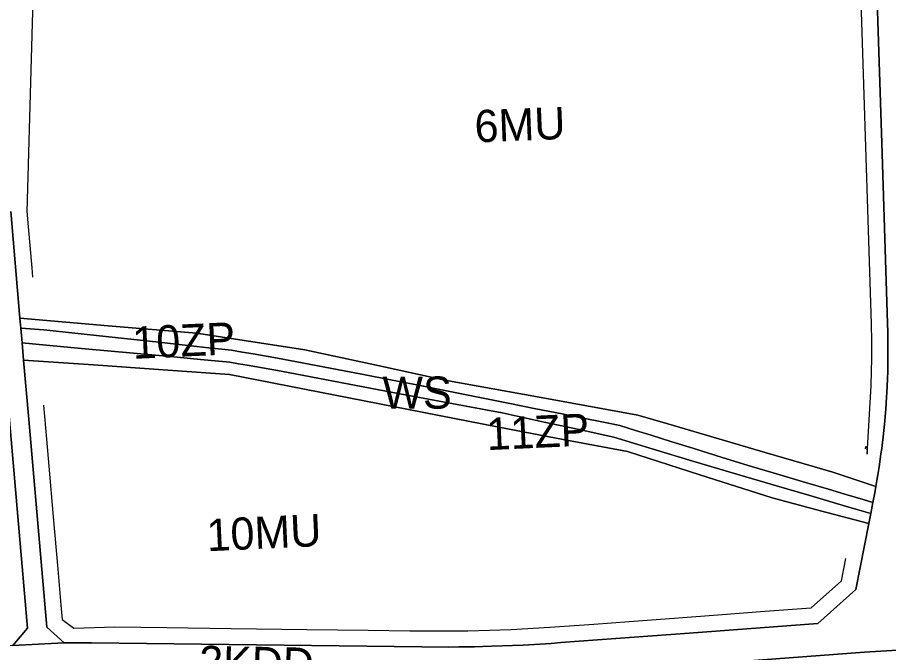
# Model space of a CAD drawing. Extents: x 7418021 to 7419743, y 5540231 to 5541685.
# Drawn here: x 7419069.1 to 7419339.9, y 5540508.6 to 5540706.1 of the extents above; entities that cross this region are included whole.
import ezdxf

# ---------------------------------------------------------------- set-up
doc = ezdxf.new("R2010")
doc.units = 0
for name, color, linetype in [('linie_rozgraniczajace', 7, 'Continuous'), ('linie_zabudowy_nieprzekraczalne', 7, 'Continuous'), ('oznaczenia_przeznaczen', 7, 'Continuous')]:
    doc.layers.add(name, color=color, linetype=linetype)

msp = doc.modelspace()

# ---------------------------------------------------------------- linework, layer by layer
at = {"layer": 'linie_rozgraniczajace'}
for points in [[(7419336.33, 5540711.28), (7419337.76, 5540666.96), (7419339.58, 5540611.01), (7419339.63, 5540608.2), (7419339.69, 5540605.39), (7419339.69, 5540602.6), (7419339.68, 5540599.81), (7419339.64, 5540597.92), (7419339.6, 5540596.04), (7419339.51, 5540593.68), (7419339.42, 5540591.32), (7419339.33, 5540589.6), (7419339.23, 5540587.87), (7419338.98, 5540584.26), (7419338.58, 5540579.65), (7419338.38, 5540577.68), (7419338.17, 5540575.7), (7419337.95, 5540573.89), (7419337.73, 5540572.07), (7419337.51, 5540570.43), (7419337.29, 5540568.79), (7419336.92, 5540566.32), (7419336.54, 5540563.85), (7419336.24, 5540562.07), (7419335.94, 5540560.28), (7419322.52, 5540564.68), (7419301.55, 5540570.84), (7419271.24, 5540579.7), (7419261.92, 5540582.4), (7419231.92, 5540587.88), (7419201.91, 5540593.35), (7419180.19, 5540598.05), (7419158.46, 5540602.74), (7419141.6, 5540605.33), (7419124.73, 5540607.91), (7419097.29, 5540610.25), (7419069.85, 5540612.59), (7419066.98, 5540645.75)], [(7419067.63, 5540510.82), (7419083.62, 5540511.65), (7419092.09, 5540511.68), (7419143.41, 5540511.02), (7419194.73, 5540510.36), (7419203.14, 5540510.33), (7419206.29, 5540510.35), (7419211.12, 5540510.42), (7419213.61, 5540510.48), (7419216.4, 5540510.56), (7419219.75, 5540510.67), (7419222.99, 5540510.8), (7419226.26, 5540510.96), (7419235.02, 5540511.48), (7419237.94, 5540511.69), (7419277.9, 5540514.67), (7419317.85, 5540517.65), (7419323.79, 5540522.93), (7419329.73, 5540528.21), (7419333.72, 5540548.71), (7419334.34, 5540551.87), (7419335, 5540555.32), (7419335.57, 5540558.3), (7419335.94, 5540560.28), (7419336.24, 5540562.07), (7419336.54, 5540563.85), (7419336.92, 5540566.32), (7419337.29, 5540568.79), (7419337.51, 5540570.43), (7419337.73, 5540572.07), (7419337.95, 5540573.89), (7419338.17, 5540575.7), (7419338.38, 5540577.68), (7419338.58, 5540579.65), (7419338.98, 5540584.26), (7419339.23, 5540587.87), (7419339.33, 5540589.6), (7419339.42, 5540591.32), (7419339.51, 5540593.68), (7419339.6, 5540596.04), (7419339.64, 5540597.92), (7419339.68, 5540599.81), (7419339.69, 5540602.6), (7419339.69, 5540605.39), (7419339.63, 5540608.2), (7419339.58, 5540611.01), (7419337.76, 5540666.96), (7419336.33, 5540711.28)], [(7419066.98, 5540645.75), (7419069.85, 5540612.59), (7419070.12, 5540609.45), (7419070.52, 5540604.88), (7419070.98, 5540599.56), (7419072.58, 5540581.12), (7419078.18, 5540516.49), (7419083.62, 5540511.65), (7419067.63, 5540510.82), (7419072.18, 5540516.17), (7419066.58, 5540580.83)], [(7419393.57, 5540512.42), (7419332.34, 5540508.71), (7419285.51, 5540505.21)], [(7419285.51, 5540505.21), (7419332.34, 5540508.71), (7419393.57, 5540512.42)]]:
    msp.add_lwpolyline(points, dxfattribs=at)
for points in [[(7419069.85, 5540612.59), (7419097.29, 5540610.25), (7419124.73, 5540607.91), (7419141.6, 5540605.33), (7419158.46, 5540602.74), (7419180.19, 5540598.05), (7419201.91, 5540593.35), (7419231.92, 5540587.88), (7419261.92, 5540582.4), (7419271.24, 5540579.7), (7419301.55, 5540570.84), (7419322.52, 5540564.68), (7419335.94, 5540560.28), (7419335.57, 5540558.3), (7419335, 5540555.32), (7419331.92, 5540556.22), (7419326.24, 5540557.9), (7419321.22, 5540559.37), (7419314.09, 5540561.49), (7419304.04, 5540564.47), (7419297.27, 5540566.48), (7419288.14, 5540569.3), (7419279.02, 5540572.12), (7419272.53, 5540574.15), (7419266.03, 5540576.17), (7419261.19, 5540577.68), (7419256.35, 5540579.19), (7419252.76, 5540579.94), (7419249.16, 5540580.68), (7419243.79, 5540581.75), (7419238.42, 5540582.81), (7419230.26, 5540584.43), (7419222.1, 5540586.05), (7419212.29, 5540588), (7419202.47, 5540589.95), (7419193.74, 5540591.78), (7419189.39, 5540592.6), (7419185.04, 5540593.41), (7419176.15, 5540595.13), (7419166.84, 5540596.94), (7419157.53, 5540598.75), (7419149.93, 5540600.11), (7419142.33, 5540601.48), (7419138.96, 5540602.06), (7419135.59, 5540602.63), (7419131.56, 5540603.07), (7419127.54, 5540603.5), (7419112.98, 5540605.09), (7419096.55, 5540606.87), (7419077.26, 5540608.95), (7419070.12, 5540609.45)], [(7419070.12, 5540609.45), (7419077.26, 5540608.95), (7419096.55, 5540606.87), (7419112.98, 5540605.09), (7419127.54, 5540603.5), (7419131.56, 5540603.07), (7419135.59, 5540602.63), (7419138.96, 5540602.06), (7419142.33, 5540601.48), (7419149.93, 5540600.11), (7419157.53, 5540598.75), (7419166.84, 5540596.94), (7419176.15, 5540595.13), (7419185.04, 5540593.41), (7419189.39, 5540592.6), (7419193.74, 5540591.78), (7419202.47, 5540589.95), (7419212.29, 5540588), (7419222.1, 5540586.05), (7419230.26, 5540584.43), (7419238.42, 5540582.81), (7419243.79, 5540581.75), (7419249.16, 5540580.68), (7419252.76, 5540579.94), (7419256.35, 5540579.19), (7419261.19, 5540577.68), (7419266.03, 5540576.17), (7419272.53, 5540574.15), (7419279.02, 5540572.12), (7419288.14, 5540569.3), (7419297.27, 5540566.48), (7419304.04, 5540564.47), (7419314.09, 5540561.49), (7419321.22, 5540559.37), (7419326.24, 5540557.9), (7419331.92, 5540556.22), (7419335, 5540555.32), (7419334.34, 5540551.87), (7419330.04, 5540553.13), (7419325.74, 5540554.39), (7419315.36, 5540557.43), (7419304.98, 5540560.47), (7419292.01, 5540564.32), (7419279.05, 5540568.16), (7419266.74, 5540571.88), (7419254.44, 5540575.61), (7419243.65, 5540577.94), (7419232.85, 5540580.28), (7419226.3, 5540581.7), (7419219.74, 5540583.12), (7419214.7, 5540584.05), (7419187.95, 5540589.08), (7419151.06, 5540596.15), (7419145.26, 5540597.15), (7419140.48, 5540597.97), (7419137.77, 5540598.43), (7419135.05, 5540598.9), (7419132.8, 5540599.11), (7419130.55, 5540599.32), (7419128.24, 5540599.53), (7419125.93, 5540599.75), (7419117.72, 5540600.52), (7419105.16, 5540601.69), (7419090.08, 5540603.1), (7419077.99, 5540604.23), (7419070.52, 5540604.88)], [(7418938.17, 5540602.64), (7418963.79, 5540604.94), (7418989.41, 5540607.25), (7419027.14, 5540603.92), (7419064.86, 5540600.6), (7419066.58, 5540580.83), (7419072.18, 5540516.17), (7419067.63, 5540510.82), (7419055.07, 5540509.46), (7418984.43, 5540500.04), (7418913.79, 5540490.61), (7418910.2, 5540494.76), (7418921.59, 5540534.82), (7418932.97, 5540574.89), (7418935.14, 5540583.49), (7418936.07, 5540587.9), (7418936.64, 5540591.04), (7418937.19, 5540594.46), (7418937.41, 5540596.09), (7418937.82, 5540599.28), (7418938, 5540600.85)], [(7419070.52, 5540604.88), (7419077.99, 5540604.23), (7419090.08, 5540603.1), (7419105.16, 5540601.69), (7419117.72, 5540600.52), (7419125.93, 5540599.75), (7419128.24, 5540599.53), (7419130.55, 5540599.32), (7419132.8, 5540599.11), (7419135.05, 5540598.9), (7419137.77, 5540598.43), (7419140.48, 5540597.97), (7419145.26, 5540597.15), (7419151.06, 5540596.15), (7419187.95, 5540589.08), (7419214.7, 5540584.05), (7419219.74, 5540583.12), (7419226.3, 5540581.7), (7419232.85, 5540580.28), (7419243.65, 5540577.94), (7419254.44, 5540575.61), (7419266.74, 5540571.88), (7419279.05, 5540568.16), (7419292.01, 5540564.32), (7419304.98, 5540560.47), (7419315.36, 5540557.43), (7419325.74, 5540554.39), (7419330.04, 5540553.13), (7419334.34, 5540551.87), (7419333.72, 5540548.71), (7419318.68, 5540552.69), (7419303.65, 5540556.68), (7419281.17, 5540563.88), (7419258.7, 5540571.08), (7419238.71, 5540574.88), (7419218.72, 5540578.67), (7419176.88, 5540586.87), (7419135.04, 5540595.07), (7419124.71, 5540595.81), (7419114.38, 5540596.55), (7419092.68, 5540598.05), (7419070.98, 5540599.56)], [(7419070.98, 5540599.56), (7419092.68, 5540598.05), (7419114.38, 5540596.55), (7419124.71, 5540595.81), (7419135.04, 5540595.07), (7419176.88, 5540586.87), (7419218.72, 5540578.67), (7419238.71, 5540574.88), (7419258.7, 5540571.08), (7419281.17, 5540563.88), (7419303.65, 5540556.68), (7419318.68, 5540552.69), (7419333.72, 5540548.71), (7419329.73, 5540528.21), (7419323.79, 5540522.93), (7419317.85, 5540517.65), (7419277.9, 5540514.67), (7419237.94, 5540511.69), (7419235.02, 5540511.48), (7419226.26, 5540510.96), (7419222.99, 5540510.8), (7419219.75, 5540510.67), (7419216.4, 5540510.56), (7419213.61, 5540510.48), (7419211.12, 5540510.42), (7419206.29, 5540510.35), (7419203.14, 5540510.33), (7419194.73, 5540510.36), (7419143.41, 5540511.02), (7419092.09, 5540511.68), (7419083.62, 5540511.65), (7419078.18, 5540516.49), (7419072.58, 5540581.12)]]:
    msp.add_lwpolyline(points, close=True, dxfattribs=at)
at = {"layer": 'linie_zabudowy_nieprzekraczalne'}
for points in [[(7419075.71, 5540777.67), (7419071.98, 5540645.61)], [(7419334.58, 5540610.85), (7419331.23, 5540714.49)], [(7419071.99, 5540645.85), (7419072.41, 5540641)], [(7419072.41, 5540641), (7419073.52, 5540628.19)], [(7419073.52, 5540628.19), (7419073.76, 5540625.36)], [(7419334.7, 5540605.34), (7419334.58, 5540610.91)], [(7419334.69, 5540599.87), (7419334.7, 5540605.34)], [(7419334.61, 5540596.19), (7419334.69, 5540599.87)], [(7419334.43, 5540591.55), (7419334.61, 5540596.19)], [(7419333.26, 5540570.29), (7419334.43, 5540591.55)], [(7419077.21, 5540585.58), (7419078.13, 5540574.95)], [(7419078.13, 5540574.95), (7419078.86, 5540566.57)], [(7419332.68, 5540571.97), (7419332.78, 5540572.7)], [(7419332.78, 5540572.7), (7419332.8, 5540572.39)], [(7419332.8, 5540572.39), (7419332.97, 5540572.72)], [(7419332.97, 5540572.72), (7419333.16, 5540572.59)], [(7419333.16, 5540572.59), (7419333.26, 5540570.29)], [(7419078.86, 5540566.57), (7419080.22, 5540550.85)], [(7419080.22, 5540550.85), (7419081.64, 5540534.5)], [(7419325.24, 5540530.91), (7419326.55, 5540537.83)], [(7419081.64, 5540534.5), (7419082.6, 5540523.37)], [(7419315.8, 5540522.51), (7419325.24, 5540530.91)], [(7419082.6, 5540523.37), (7419082.99, 5540518.9)], [(7419286.79, 5540520.35), (7419301.43, 5540521.44)], [(7419301.43, 5540521.44), (7419315.8, 5540522.51)], [(7419082.99, 5540518.9), (7419086.6, 5540516.24)], [(7419259.22, 5540518.29), (7419274.6, 5540519.44)], [(7419274.6, 5540519.44), (7419286.79, 5540520.35)], [(7419086.6, 5540516.24), (7419099.34, 5540516.59)], [(7419099.34, 5540516.59), (7419115.53, 5540516.38)], [(7419115.53, 5540516.38), (7419135.48, 5540516.13)], [(7419135.48, 5540516.13), (7419159.08, 5540515.82)], [(7419222.58, 5540515.79), (7419234.62, 5540516.47)], [(7419234.62, 5540516.47), (7419248.2, 5540517.47)], [(7419248.2, 5540517.47), (7419259.22, 5540518.29)], [(7419159.08, 5540515.82), (7419178.09, 5540515.58)], [(7419178.09, 5540515.58), (7419191.04, 5540515.41)], [(7419191.04, 5540515.41), (7419196.9, 5540515.34)], [(7419196.9, 5540515.34), (7419209.13, 5540515.39)], [(7419209.13, 5540515.39), (7419222.58, 5540515.79)]]:
    msp.add_lwpolyline(points, dxfattribs=at)

# ---------------------------------------------------------------- texts
at = {"layer": 'oznaczenia_przeznaczen'}
for s, rotation, p in [('6MU', 2.2595, (7419211.36, 5540667.23)), ('10ZP', 2.669, (7419105.04, 5540599.92)), ('11ZP', 2.669, (7419215.1, 5540571.54)), ('10MU', 2.669, (7419128.1, 5540540.1)), ('2KDD', 358.8879, (7419125.46, 5540500.77))]:
    msp.add_text(s, height=10, rotation=rotation, dxfattribs=at).set_placement(p)
msp.add_text('WS', height=10, dxfattribs=at).set_placement((7419182.52, 5540584.45))

doc.saveas('drawing.dxf')
